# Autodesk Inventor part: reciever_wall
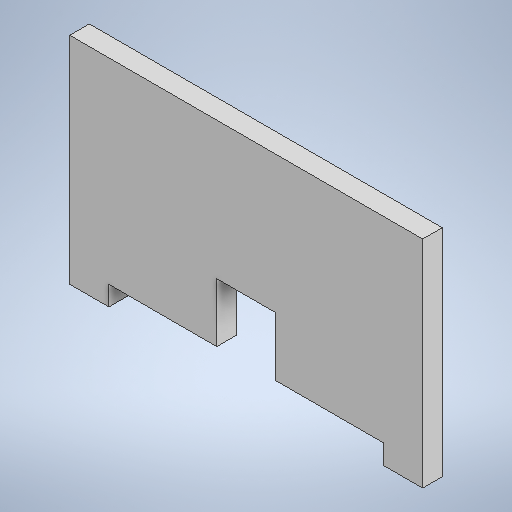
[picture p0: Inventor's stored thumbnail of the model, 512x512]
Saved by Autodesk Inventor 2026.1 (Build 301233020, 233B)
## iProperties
Created: 2026-10
Part Number: reciever_wall
Material: Generic
Document SubType Name: Modeling
Designer: alolo
Density: 1 g/cm^3
Appearance: Default
Author: alolo
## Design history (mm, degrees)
sketch "Sketch1"
  geometry: L1 (0, 0)-(90, 0); L2 (90, 0)-(90, 50); L3 (90, 50)-(0, 50); L4 (0, 50)-(0, 0); L5 (37.5, 0)-(52.5, 0); L6 (52.5, 0)-(52.5, 15); L7 (52.5, 15)-(37.5, 15); L8 (37.5, 15)-(37.5, 0); L9 (0, 0)-(10, 0); L10 (10, 0)-(10, -5); L11 (10, -5)-(0, -5); L12 (0, -5)-(0, 0); L13 (90, 0)-(80, 0); L14 (80, 0)-(80, -5); L15 (80, -5)-(90, -5); L16 (90, -5)-(90, 0); 6 further points
  constraints: 32 end point, 8 parallel, 4 horizontal, 4 perpendicular, 2 midpoint, 1 coincident, 1 point on line, 1 vertical alignment
  dimensions: "d0" = 90 distance of L3.end L2.end; "d1" = 50 distance of L3.end L1.start; "d2" = 15 distance of L7.end L6.end; "d3" = 15 distance of L6.end L5.end; "d6" = 10 distance of L10.end L11.end; "d7" = 5 distance of L9.end L10.end; "d8" = 10 distance of L15.end L14.end; "d9" = 5 distance of L14.end L13.end
extrude "Extrusion1" new body sketch "Sketch1" distance "d4" = 5 (= wood_thickness); taper "d5" = 0 deg
body "Solid1"
other parameters: "slide_length" = 195 [user parameter], "slide_angle" = 7 deg [user parameter], "slide_width" = 65 [user parameter], "wood_thickness" = 5 [user parameter; used in 1 equation term], "aclyric_thickness" = 6 [user parameter]
